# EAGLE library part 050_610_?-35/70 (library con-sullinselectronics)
.050 DIP EDGE CARD CONNECTOR .050 [1.27mm] CONTACT CENTERS .610" INSULATEOR HEIGHT Source: .050 DIP EDGE CARD.pdf
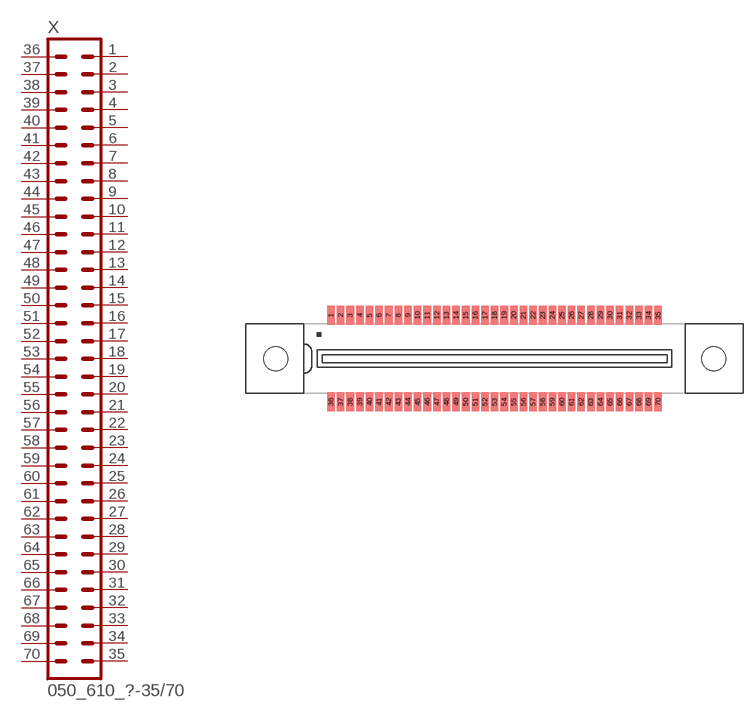
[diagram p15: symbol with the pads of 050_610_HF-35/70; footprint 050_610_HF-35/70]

Designator prefix X

## 050_610_HF-35/70 (OC_FARNELL: unknown; OC_NEWARK: unknown)  [050_610_HF-35/70]
1  1  pas
2  2  pas
3  3  pas
4  4  pas
5  5  pas
6  6  pas
7  7  pas
8  8  pas
9  9  pas
10  10  pas
11  11  pas
12  12  pas
13  13  pas
14  14  pas
15  15  pas
16  16  pas
17  17  pas
18  18  pas
19  19  pas
20  20  pas
21  21  pas
22  22  pas
23  23  pas
24  24  pas
25  25  pas
26  26  pas
27  27  pas
28  28  pas
29  29  pas
30  30  pas
31  31  pas
32  32  pas
33  33  pas
34  34  pas
35  35  pas
36  36  pas
37  37  pas
38  38  pas
39  39  pas
40  40  pas
41  41  pas
42  42  pas
43  43  pas
44  44  pas
45  45  pas
46  46  pas
47  47  pas
48  48  pas
49  49  pas
50  50  pas
51  51  pas
52  52  pas
53  53  pas
54  54  pas
55  55  pas
56  56  pas
57  57  pas
58  58  pas
59  59  pas
60  60  pas
61  61  pas
62  62  pas
63  63  pas
64  64  pas
65  65  pas
66  66  pas
67  67  pas
68  68  pas
69  69  pas
70  70  pas

## Footprint 050_610_HF-35/70 (pad centres in mm)
.050 DIP EDGE CARD CONNECTOR SURFACE MOUNT .050 [1.27mm] CONTACT CENTERS .610" INSULATEOR HEIGHT Source: .050 DIP EDGE CARD.pdf
smd 1 x 2.5: 1 -21.59,5.715; 2 -20.32,5.715; 3 -19.05,5.715; 4 -17.78,5.715; 5 -16.51,5.715; 6 -15.24,5.715; 7 -13.97,5.715; 8 -12.7,5.715; 9 -11.43,5.715; 10 -10.16,5.715; 11 -8.89,5.715; 12 -7.62,5.715; 13 -6.35,5.715; 14 -5.08,5.715; 15 -3.81,5.715; 16 -2.54,5.715; 17 -1.27,5.715; 18 0,5.715; 19 1.27,5.715; 20 2.54,5.715; 21 3.81,5.715; 22 5.08,5.715; 23 6.35,5.715; 24 7.62,5.715; 25 8.89,5.715; 26 10.16,5.715; 27 11.43,5.715; 28 12.7,5.715; 29 13.97,5.715; 30 15.24,5.715; 31 16.51,5.715; 32 17.78,5.715; 33 19.05,5.715; 34 20.32,5.715; 35 21.59,5.715; 36 -21.59,-5.715; 37 -20.32,-5.715; 38 -19.05,-5.715; 39 -17.78,-5.715; 40 -16.51,-5.715; 41 -15.24,-5.715; 42 -13.97,-5.715; 43 -12.7,-5.715; 44 -11.43,-5.715; 45 -10.16,-5.715; 46 -8.89,-5.715; 47 -7.62,-5.715; 48 -6.35,-5.715; 49 -5.08,-5.715; 50 -3.81,-5.715; 51 -2.54,-5.715; 52 -1.27,-5.715; 53 0,-5.715; 54 1.27,-5.715; 55 2.54,-5.715; 56 3.81,-5.715; 57 5.08,-5.715; 58 6.35,-5.715; 59 7.62,-5.715; 60 8.89,-5.715; 61 10.16,-5.715; 62 11.43,-5.715; 63 12.7,-5.715; 64 13.97,-5.715; 65 15.24,-5.715; 66 16.51,-5.715; 67 17.78,-5.715; 68 19.05,-5.715; 69 20.32,-5.715; 70 21.59,-5.715
hole 3.18 at -28.905,0
hole 3.18 at 28.905,0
